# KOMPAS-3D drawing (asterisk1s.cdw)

Views: View = Шестерня, Вид 2, Вид 4, Вид 5
Referenced files: Звездочка(Z=10).cdw
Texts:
  Звездочка
  Сопрягаемая
  цепь
  Диаметр делительной
  окружности
  Торцовое биение зубчатого
  венца
  Радиальное биение
  окружности впадин
  Допуск на разность шагов
  Диаметр окружности впадин
  по ГОСТ 591-69
  Профиль зуба по ГОСТ 591-69
  Число зубьев
  Расстояние
  между
  внутренними
  пластинами
  Ширина
  внутренней
  пластины
  Диаметр ролика
  Шаг
  B BH
  Cо смещением
  ПР-15,875-2300-1
  Таблица параметров
  min
  Неуказанные предельные отклонения размеров  H14; h14;    IT14 2 .
  HRC 28 ... 32.
  *Размер для справок.
  gliv
  Сталь 45 ГОСТ 1050-88
Dimensions and other numbers on the sheet: 6,48; 14,8; 51,37; 0,08; 0,025; 41,061; 10,16; 15,875; 10; 57,3; 5,88; 8,13; 17,3; 30; 6,3; 1,6; 1; 2 фаски; 3,2; 2,5; 0,6; 16; 8; 41,06; 5; 15; 18,3; 25; 9; 12,5; 6; 7; 4:1; 0,1; 0; 2; 3; 4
